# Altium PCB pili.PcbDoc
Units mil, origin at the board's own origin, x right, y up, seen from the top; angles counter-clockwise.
Board outline 3165 x 2360 mil, 2 copper layers (Top Layer, Bottom Layer); 29 components, 28 nets, 78 pads, 0 vias.
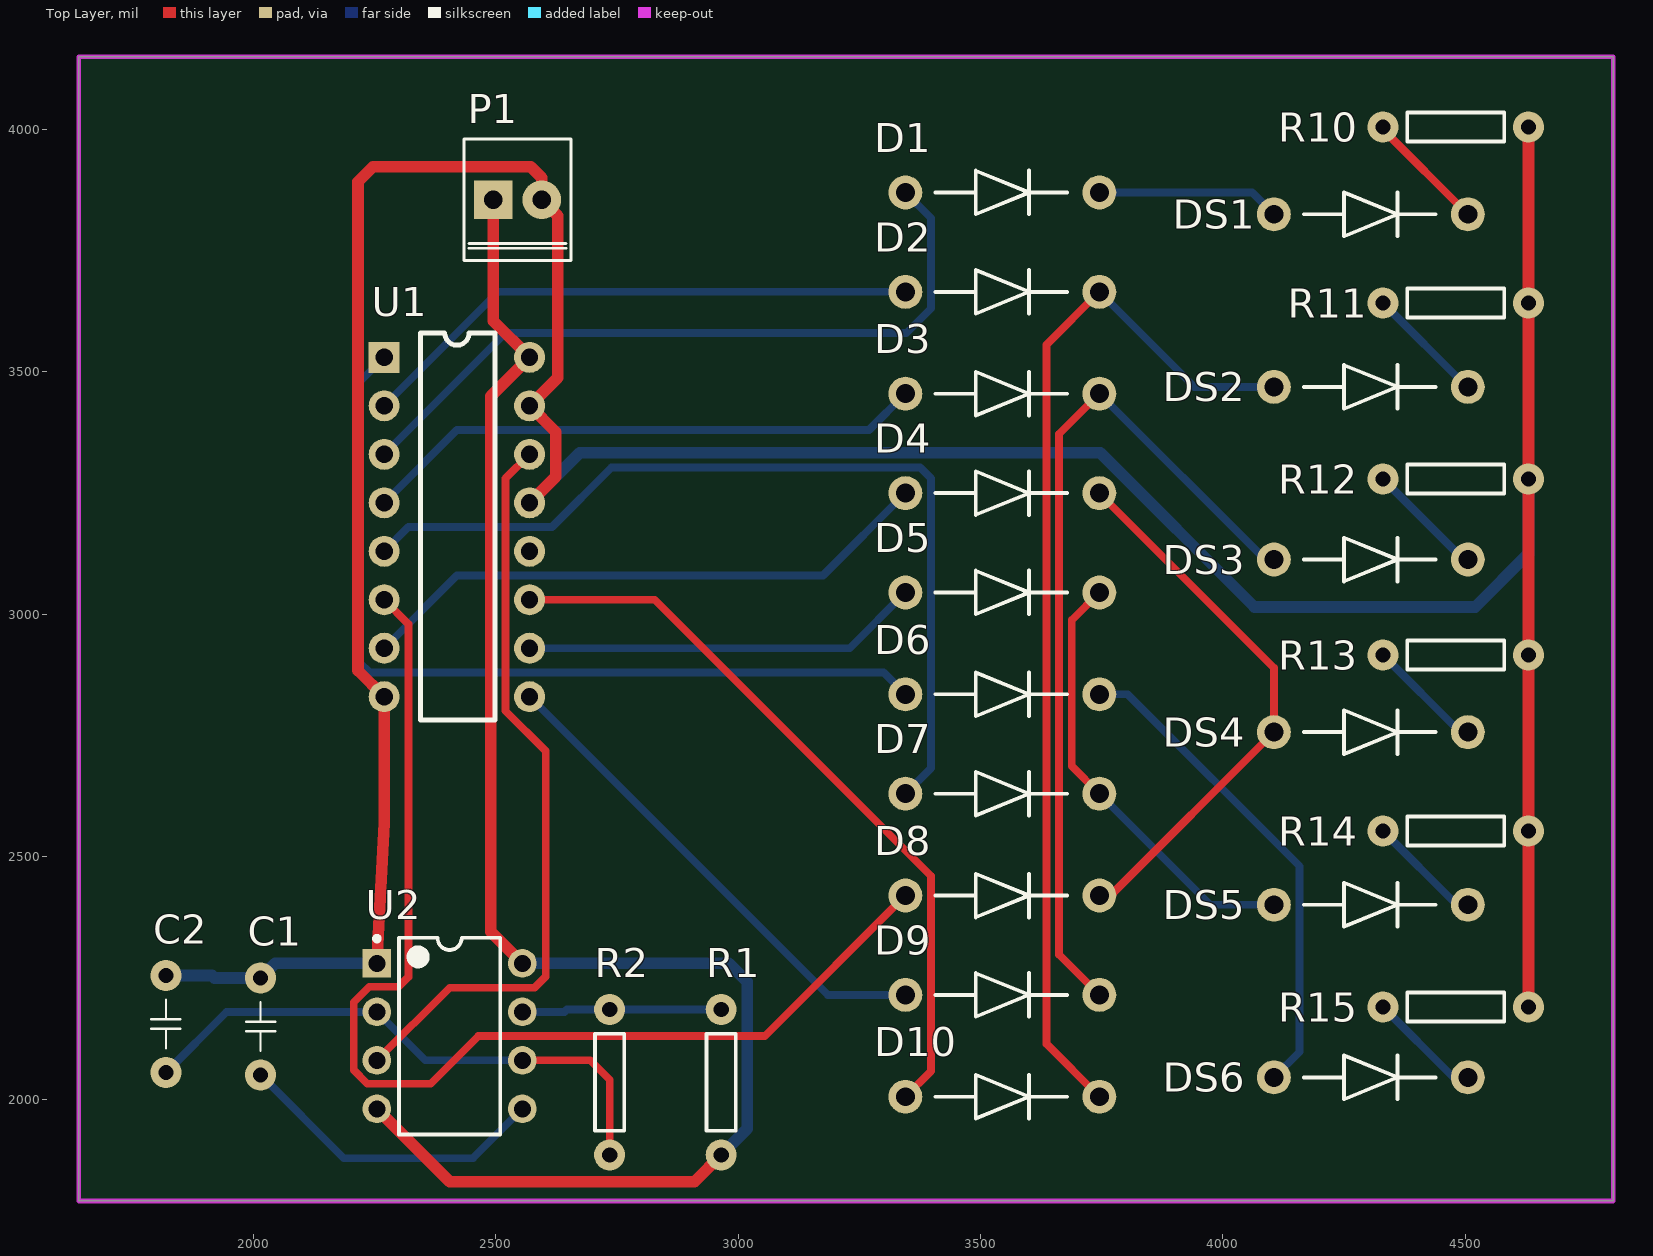
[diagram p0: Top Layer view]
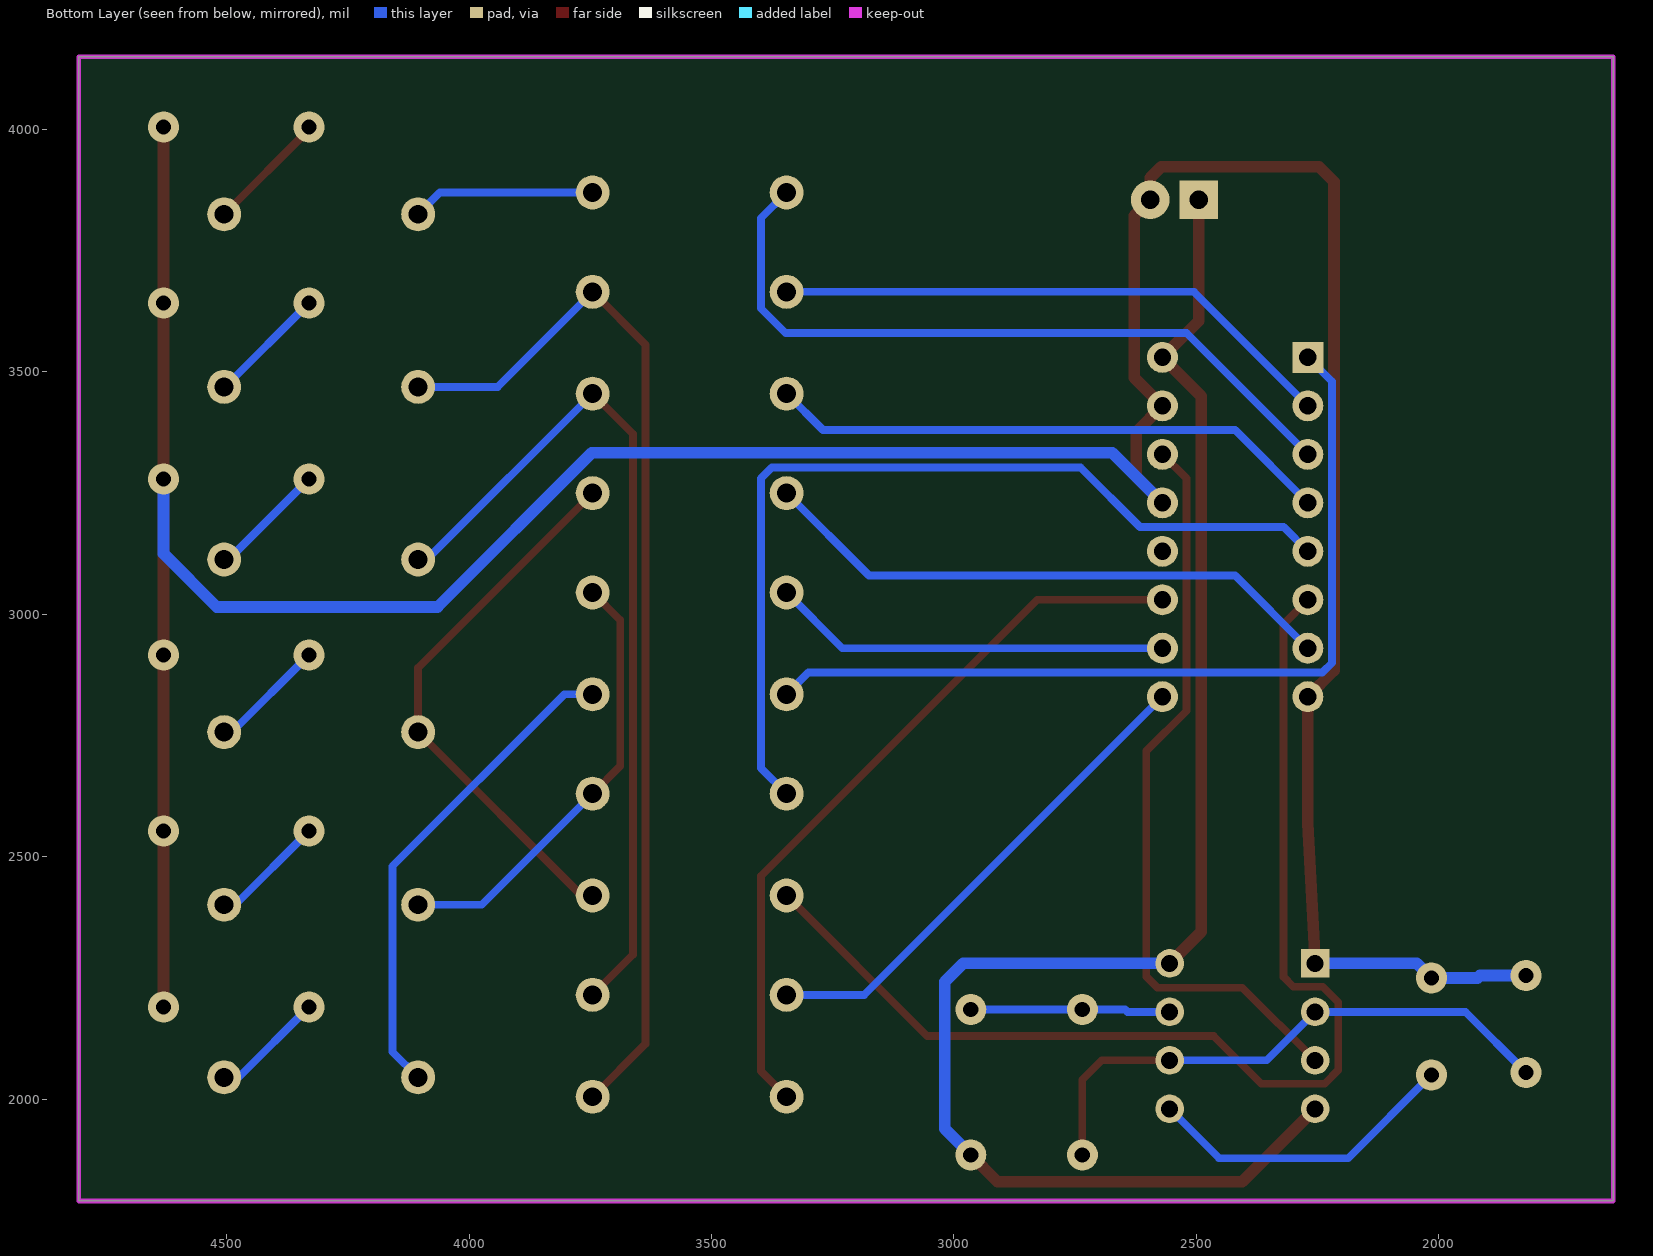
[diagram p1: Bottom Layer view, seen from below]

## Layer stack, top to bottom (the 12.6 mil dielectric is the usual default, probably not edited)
Top Layer: signal copper 1.4
Dielectric: dielectric 12.6, FR-4, Dk 4.8
Bottom Layer: signal copper 1.4

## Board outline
1640,1790 4805,1790 4805,4150 1640,4150

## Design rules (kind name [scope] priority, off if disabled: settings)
Clearance [All] p1: gap=10
PolygonConnect [All] p1: connectstyle=Relief reliefconductorwidth=10 reliefentries=4 polygonreliefangle="90 Angle" airgapwidth=10
RoutingVias [All] p1: holewidth=28 width=50 viastyle="Through Hole" minholewidth=28 minwidth=50 maxholewidth=28 maxwidth=50
SolderMaskExpansion [All] p1: expansion=4
Width Width_power [InNetClass('power')] p1: maxlimit=40 minlimit=10 preferedwidth=24
Width [All] p2: maxlimit=40 minlimit=10 preferedwidth=16
28 further rules are at their usual default settings.

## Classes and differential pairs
net class power: GND VCC

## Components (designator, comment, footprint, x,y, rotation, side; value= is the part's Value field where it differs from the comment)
C1 "Cap" "C200 - 1" 2015,2150 r180 top
C2 "Cap" "C200 - 1" 1820,2155 r180 top
D1 "1N914" D400 3545,3870 r0 top
D2 "1N914" D400 3545,3665 r0 top
D3 "1N914" D400 3545,3455 r0 top
D4 "1N914" D400 3545,3250 r0 top
D5 "1N914" D400 3545,3045 r0 top
D6 "1N914" D400 3545,2835 r0 top
D7 "1N914" D400 3545,2630 r0 top
D8 "1N914" D400 3545,2420 r0 top
D9 "1N914" D400 3545,2215 r0 top
D10 "1N914" D400 3545,2005 r0 top
DS1 "1N914" D400-1 4305,3825 r0 top
DS2 "1N914" D400-1 4305,3469 r0 top
DS3 "1N914" D400-1 4305,3113 r0 top
DS4 "1N914" D400-1 4305,2757 r0 top
DS5 "1N914" D400-1 4305,2401 r0 top
DS6 "1N914" D400-1 4305,2045 r0 top
P1 "+5V" "HEADER 2 PW-0.2" 2545,3855 r270 top
R1 "1k" AXIAL-0.3 2965,2035 r270 top
R2 "1k" AXIAL-0.3 2735,2035 r90 top
R10 "1k" AXIAL-0.3 4480,4005 r180 top
R11 "1k" AXIAL-0.3 4480,3642 r180 top
R12 "1k" AXIAL-0.3 4480,3279 r180 top
R13 "1k" AXIAL-0.3 4480,2916 r180 top
R14 "1k" AXIAL-0.3 4480,2553 r180 top
R15 "1k" AXIAL-0.3 4480,2190 r180 top
U1 "CD4017BCN" DIP16_4017 2270,3530 r270 top
U2 "LMC555CN" N08E_555 2405,2130 r0 top

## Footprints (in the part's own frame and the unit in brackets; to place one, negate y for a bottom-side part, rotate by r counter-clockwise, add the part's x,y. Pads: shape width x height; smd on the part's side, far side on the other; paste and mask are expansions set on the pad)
AXIAL-0.3 [mil] "0.3\" Resistor; 2 Leads"
  round 64 hole 31.5: 1(-150,0) 2(150,0)
  silkscreen extent -100,-30 100,30, body extent -161,-41 165,41, height 88
"C200 - 1" [mil] "吵病筿甧竟"
  round 64 hole 31.5: 1(0,100) 2(0,-100)
  silkscreen extent -30,-50 30,50, body extent -19,-132 21,143, height 282
D400 [mil]
  round 70 hole 39: 1(-200,0) 2(200,0)
  silkscreen extent -138,-45 134,45, body extent -216,-79 217,78, height 161
D400-1 [mil]
  round 70 hole 39: 1(-200,0) 2(200,0)
  silkscreen extent -138,-45 134,45, body extent -216,-59 217,59, height 141
DIP16_4017 [mil] "4017"
  rect 64x64 hole 35.43: 1(0,0)
  round 64 hole 35.43: 2(100,0) 3(200,0) 4(300,0) 5(400,0) 6(500,0) 7(600,0) 8(700,0) 9(700,300) 10(600,300) 11(500,300) 12(400,300) 13(300,300) 14(200,300) 15(100,300) 16(0,300)
  silkscreen extent -50,75 748,228, body extent -50,-4 748,304, height 177
"HEADER 2 PW-0.2" [mil]
  rect 80x80 hole 39: 1(0,-50)
  round 80 hole 39: 2(0,50)
  silkscreen extent -125,-110 125,110, body extent -124,-110 125,113, height 433
N08E_555 [mm]
  rect 1.5x1.5 hole 0.9: 1(-3.81,3.81)
  round 1.5 hole 0.9: 2(-3.81,1.27) 3(-3.81,-1.27) 4(-3.81,-3.81) 5(3.81,-3.81) 6(3.81,-1.27) 7(3.81,1.27) 8(3.81,3.81)
  silkscreen extent -3.93,-5.15 2.65,5.23, body extent -3.92,-5.15 3.92,5.15, height 4.5

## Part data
C1 C2: "Capacitor"
D1 D2 D3 D4 D5 D6 D7 D8 D9 D10 DS1 DS2 DS3 DS4 DS5 DS6: "High Conductance Fast Diode"
P1: library part "Header 2", "Header, 2-Pin"
R1 R2 R10 R11 R12 R13 R14 R15: library part Res, "Resistor"
U1: "Decade Counter/Divider with 10 Decoded Outputs"
U2: "CMOS Timer"

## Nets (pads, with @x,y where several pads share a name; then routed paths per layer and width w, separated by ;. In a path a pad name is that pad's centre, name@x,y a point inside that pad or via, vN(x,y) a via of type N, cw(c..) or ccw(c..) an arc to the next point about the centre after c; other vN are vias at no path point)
GND: C1.2 C2.2 P1.2 R10.1 R11.1 R12.1 R13.1 R14.1 R15.1 U1.8 U1.13 U1.15 U2.1 | length 7487
  Top Layer w24: U2.1 2270,2570 U1.8 2216,2884 2216,3892 2247,3923 2572,3923 2595,3900 P1.2 2628,3822 2628,3488 U1.15 2624,3376 2624,3284 U1.13 ; R15.1 R14.1 R13.1 R12.1 R11.1 R10.1
  Bottom Layer w24: C2.2 1915,2255 1920,2250 C1.2 2045,2280 U2.1 ; U1.13 2673,3333 3747,3333 4065,3015 4520,3015 4630,3125 R12.1
NetC1_1: C1.1 U2.5 | length 653.5
  Bottom Layer w16: C1.1 2187,1878 2453,1878 U2.5
NetD1_1: D1.1 U1.3 | length 1513.6
  Bottom Layer w16: U1.3 2520,3580 3347,3580 3398,3631 3398,3817 D1.1
NetD2_1: D2.1 U1.2 | length 1172.3
  Bottom Layer w16: U1.2 2505,3665 D2.1
NetD3_1: D3.1 U1.4 | length 1168.2
  Bottom Layer w16: U1.4 2420,3380 3270,3380 D3.1
NetD4_1: D4.1 U1.7 | length 1207.5
  Bottom Layer w16: U1.7 2420,3080 3175,3080 D4.1
NetD5_1: D5.1 U1.10 | length 822.6
  Bottom Layer w16: U1.10 3230,2930 D5.1
NetD6_1: D6.1 U1.1 | length 1802.6
  Bottom Layer w16: U1.1 2220,3480 2220,2900 2240,2880 3300,2880 D6.1
NetD7_1: D7.1 U1.5 | length 1881.1
  Bottom Layer w16: U1.5 2320,3180 2616,3180 2739,3303 3375,3303 3398,3280 3398,2683 D7.1
NetD8_1: D8.1 U1.6 | length 2383.6
  Top Layer w16: U1.6 2320,2980 2320,2252 2300,2232 2239,2232 2207,2200 2207,2060 2235,2032 2366,2032 2464,2130 3055,2130 D8.1
NetD9_1: D9.1 U1.9 | length 1029.7
  Bottom Layer w16: U1.9 3185,2215 D9.1
NetD10_1: D10.1 U1.11 | length 1541.1
  Top Layer w16: U1.11 2828,3030 3398,2460 3398,2058 D10.1
NetDS1_2: DS1.2 R10.2 | length 252.5
  Top Layer w16: R10.2 4330,4000 DS1.2
NetDS2_2: DS2.2 R11.2 | length 246.7
  Bottom Layer w16: R11.2 4503,3469 DS2.2
NetDS3_2: DS3.2 R12.2 | length 243.8
  Bottom Layer w16: R12.2 4496,3113 DS3.2
NetDS4_2: DS4.2 R13.2 | length 240.9
  Bottom Layer w16: R13.2 4489,2757 DS4.2
NetDS5_2: DS5.2 R14.2 | length 238
  Bottom Layer w16: R14.2 4482,2401 DS5.2
NetDS6_2: DS6.2 R15.2 | length 235.1
  Bottom Layer w16: R15.2 4475,2045 DS6.2
NetR1_1: R1.1 R2.2 U2.7 | length 412.1
  Bottom Layer w16: U2.7 2642,2180 2647,2185 R2.2 R1.1
O1: D1.2 DS1.1 | length 378.6
  Bottom Layer w16: D1.2 4060,3870 DS1.1
O2: D2.2 D10.2 DS2.1 | length 2191.5
  Top Layer w16: D10.2 3636,2114 3636,3556 D2.2
  Bottom Layer w16: D2.2 3941,3469 DS2.1
O3: D3.2 D9.2 DS3.1 | length 1810.4
  Top Layer w16: D9.2 3662,2298 3662,3372 D3.2
  Bottom Layer w16: D3.2 4087,3113 DS3.1
O4: D4.2 D8.2 DS4.1 | length 1141.7
  Top Layer w16: D8.2 3768,2420 DS4.1 4105,2890 D4.2
O5: D5.2 D7.2 DS5.1 | length 917.1
  Top Layer w16: D7.2 3688,2687 3688,2988 D5.2
  Bottom Layer w16: D7.2 3974,2401 DS5.1
O6: D6.2 DS6.1 | length 1017
  Bottom Layer w16: D6.2 3803,2835 4158,2480 4158,2098 DS6.1
OUT: U1.14 U2.3 | length 1551.7
  Top Layer w16: U2.3 2405,2230 2580,2230 2603,2253 2603,2718 2520,2801 2520,3280 U1.14
TR: C2.1 R2.1 U2.2 U2.6 | length 1179.8
  Top Layer w16: U2.6 2695,2080 2735,2040 R2.1
  Bottom Layer w16: C2.1 1945,2180 U2.2 2355,2080 U2.6
VCC: P1.1 R1.2 U1.16 U2.4 U2.8 | length 3320.1
  Top Layer w24: U2.4 2405,1830 2910,1830 R1.2 ; P1.1 2495,3605 U1.16 2490,3450 2490,2345 U2.8
  Bottom Layer w24: U2.8 2981,2280 3019,2242 3019,1939 R1.2
pads on no net: U1.12

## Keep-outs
Keep-Out Layer:
  the board outline again, w10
